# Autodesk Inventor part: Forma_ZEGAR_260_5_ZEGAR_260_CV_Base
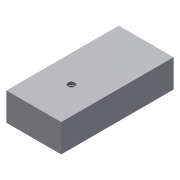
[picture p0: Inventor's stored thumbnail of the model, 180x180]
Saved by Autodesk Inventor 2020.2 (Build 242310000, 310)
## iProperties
Created: 2015-01
Part Number: Forma_ZEGAR_260_5_ZEGAR_260_CV_Base
Material: Ogólny
Document SubType Name: Modeling
Designer: F.Stasiak
Density: 1 g/cm^3
Appearance: Domyślna
Catalog Web Link: www.expertbooks.pl
Manager: www.cadconsulting.pl
Company: Fabian Stasiak CAD Consulting
Author: F.Stasiak
Subject: Zbiór ćwiczeń. Autodesk Inventor 2020. Kurs Professional
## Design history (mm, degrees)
node "Forma_ZEGAR_260_4_ZEGAR_260_MP"
sketch "Szkic1"
  geometry: 1 further point
hole "Otwór1" sketch "Szkic1" at (39, -106.407) diameter "d0" = 7; stored, may be unused: countersink angle "d4" = 90 deg, drill point angle "d6" = 118 deg; dims "d1" = 6, "d2" = 10, "d3" = 4, "d5" = 15
feature "Rzeźbienie2"
feature "Bryła4::Forma_ZEGAR_260_4_ZEGAR_260_MP"
tag "Bryła wyprowadzona1"
node "Bryła1"
feature "Forma_ZEGAR_260_4_ZEGAR_260_MP_Bodies"
feature "Powierzchnia2"
body "Srf2"
